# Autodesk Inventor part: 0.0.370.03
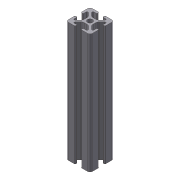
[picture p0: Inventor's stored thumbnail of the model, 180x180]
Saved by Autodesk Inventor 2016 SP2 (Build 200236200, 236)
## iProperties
Created: 2017-10
Part Number: 0.0.370.03
Material: Aluminium - 6061
Vendor: Item
Document SubType Name: Modeling
Designer: CAD Team Handzik
Density: 2.71 g/cm^3
Appearance: Aluminium - flach
Category: natur
Company: CAD Team Handzik
Title: Profil 5 20x20
Subject: Muster für iPart Modul
Author: CAD Team Handzik
MT_KOPF: =<CPR_ZEICHNR> - <CPR_SHORT>
LANG: 100,000 mm
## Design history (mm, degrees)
derived "0.0.370.03.ipt"
feature "Volumenkörper3::0.0.370.03.ipt"
tag "Bezeichnung1"
node "Volumenkörper1"
other parameters: "d11" = 0, "LANG" = 100
